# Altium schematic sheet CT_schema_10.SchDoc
size 274 x 160 mm
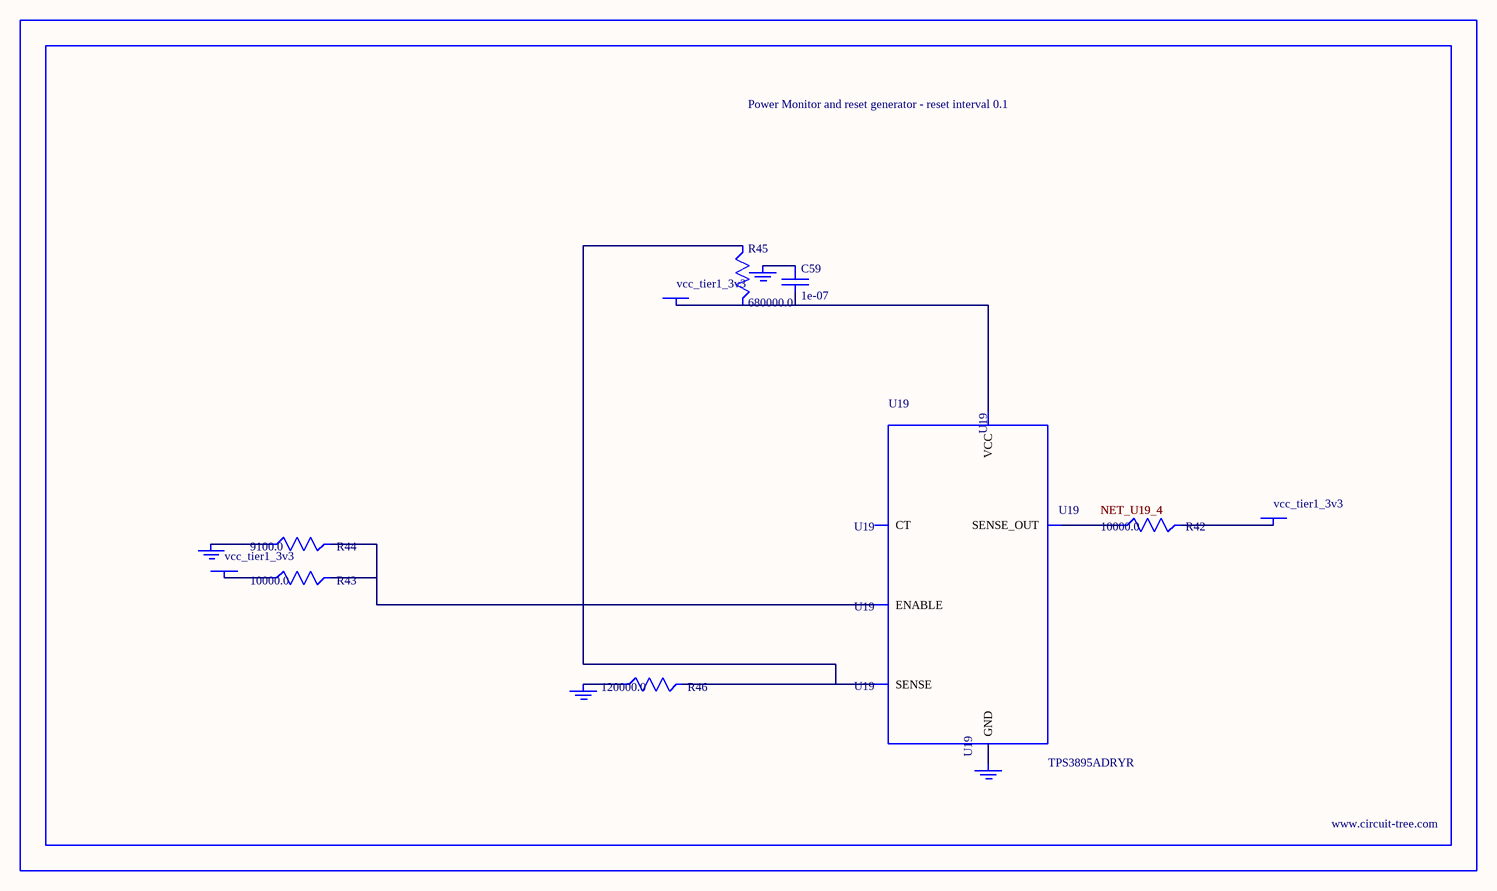
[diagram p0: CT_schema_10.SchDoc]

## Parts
BORDER9  (no value)
C59  1e-07  [C0402]
GND_INSTANCE_9_0  (no value)
GND_INSTANCE_9_1  (no value)
GND_INSTANCE_9_2  (no value)
GND_INSTANCE_9_3  (no value)
POWER_INSTANCE_9_0  vcc_tier1_3v3
POWER_INSTANCE_9_1  vcc_tier1_3v3
POWER_INSTANCE_9_2  vcc_tier1_3v3
R42  10000.0  [R0603]
R43  10000.0  [R0603]
R44  9100.0  [R0603]
R45  680000.0  [R0603]
R46  120000.0  [R0603]
U19  TPS3895ADRYR  [SON-6]

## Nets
NetC59_1: C59.1 GND_INSTANCE_9_2.0(GND)
NetC59_2: C59.2 POWER_INSTANCE_9_2.0(PWR) R45.2 U19.6(VCC)
NetGND_INSTANCE_9_0_0: GND_INSTANCE_9_0.0(GND) R44.1
NetGND_INSTANCE_9_1_0: GND_INSTANCE_9_1.0(GND) R46.1
NetGND_INSTANCE_9_3_0: GND_INSTANCE_9_3.0(GND) U19.2(GND)
NetPOWER_INSTANCE_9_0_0: POWER_INSTANCE_9_0.0(PWR) R43.1
NetPOWER_INSTANCE_9_1_0: POWER_INSTANCE_9_1.0(PWR) R42.2
NetR42_1: R42.1 U19.4(SENSE_OUT)
NetR43_2: R43.2 R44.2 U19.1(ENABLE)
NetR45_1: R45.1 R46.2 U19.3(SENSE)

Not connected (* = marked no-connect by the designer): U19 5(CT)

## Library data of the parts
BORDER9 = BORDER_PAGE9
C59 = C0402C104K3RACTU
GND_INSTANCE_9_0-GND_INSTANCE_9_3 = GND
POWER_INSTANCE_9_0-POWER_INSTANCE_9_2 = PWR
R42 R43 = RC0603JR-0710KL
R44 = RC0603JR-079K1L
R45 = RC0603JR-07680KL
R46 = RC0603JR-07120KL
